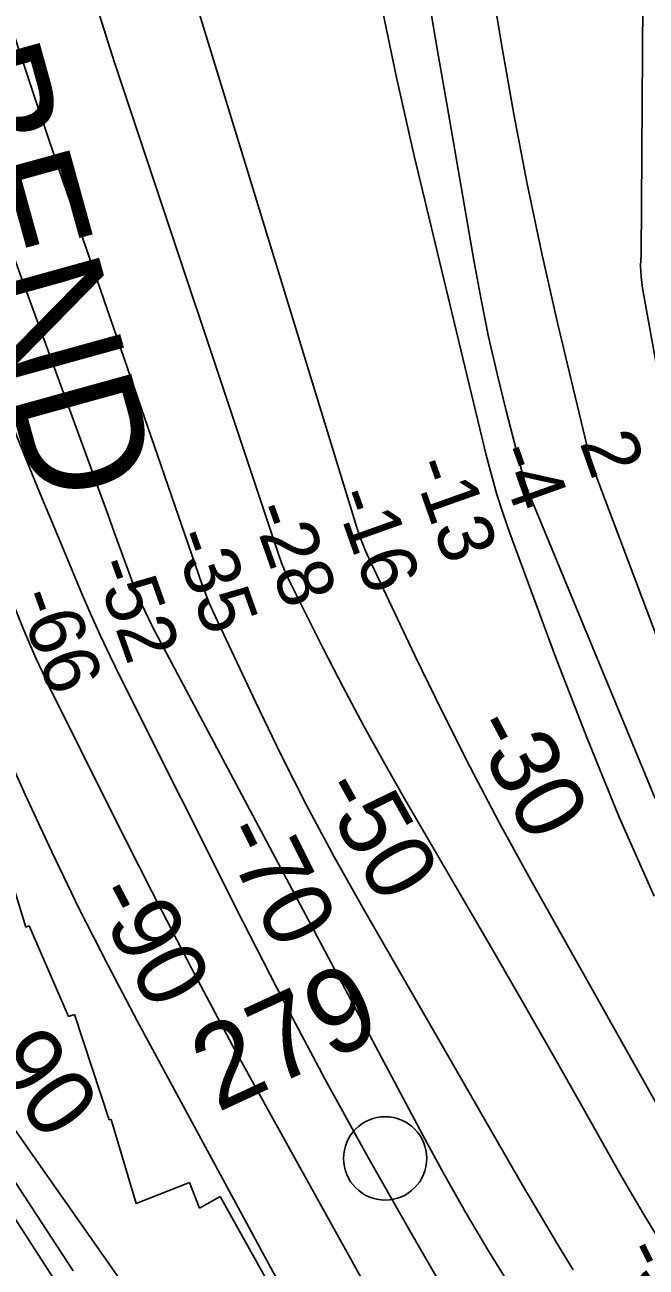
# Model space of a CAD drawing. Extents: x 3177185 to 3215018, y 812988 to 838321.
# Drawn here: x 3198092 to 3198839, y 819169 to 820661 of the extents above; entities that cross this region are included whole.
import ezdxf

# ---------------------------------------------------------------- set-up
doc = ezdxf.new("R2010")
doc.units = 0
for name, color, linetype in [('V-RIVR-IDEN', 7, 'Continuous'), ('V-RIVR-MILE', 7, 'Continuous'), ('V-RIVR-RANG', 7, 'Continuous'), ('V-RRAP-RVMT', 7, 'Continuous'), ('V-TOPO-DPTH', 7, 'Continuous'), ('V-TOPO-MAJR', 7, 'Continuous'), ('V-TOPO-MAJR-IDEN', 7, 'Continuous'), ('V-TOPO-MINR', 7, 'Continuous'), ('V-TOPO-MINR-IDEN', 7, 'Continuous')]:
    doc.layers.add(name, color=color, linetype=linetype)

msp = doc.modelspace()

# ---------------------------------------------------------------- linework, layer by layer
at = {"layer": 'V-RIVR-MILE'}
msp.add_circle((3198525.1, 819300), 50, dxfattribs=at)
at = {"layer": 'V-RRAP-RVMT'}
for p, q in [((3198093.6, 819577.8), (3198069.1, 819657.7)), ((3198097.4, 819579.5), (3198093.6, 819577.8)), ((3198144.8, 819470.4), (3198097.4, 819579.5)), ((3198152, 819472.8), (3198144.8, 819470.4)), ((3198193.7, 819346.2), (3198152, 819472.8)), ((3198196, 819346.8), (3198193.7, 819346.2)), ((3198226.1, 819246), (3198196, 819346.8)), ((3198289.9, 819271), (3198226.1, 819246)), ((3198302, 819240.3), (3198289.9, 819271)), ((3198326.8, 819254.1), (3198302, 819240.3)), ((3198381.1, 819157.2), (3198326.8, 819254.1))]:
    msp.add_line(p, q, dxfattribs=at)
at = {"layer": 'V-TOPO-DPTH'}
for points in [[(3198589.7, 821094.6), (3198664.8, 820638.2), (3198679.6, 820554.2), (3198695.5, 820470.3), (3198713.2, 820386.9), (3198732.2, 820303.6), (3198765.2, 820165), (3198768.7, 820151.3), (3198772.6, 820137.8), (3198777, 820124.3), (3198781.7, 820111), (3198927.4, 819724.6)], [(3198927.4, 819724.6), (3198781.7, 820111), (3198777, 820124.3), (3198772.6, 820137.8), (3198768.7, 820151.3), (3198765.2, 820165), (3198732.2, 820303.6), (3198713.2, 820386.9), (3198695.5, 820470.3), (3198679.6, 820554.2), (3198664.8, 820638.2), (3198589.7, 821094.6)], [(3198959.4, 819172.7), (3198698.1, 819637.9), (3198662.1, 819703.6), (3198627.1, 819769.7), (3198593.4, 819836.6), (3198560.7, 819904), (3198505.4, 820021.1), (3198501.2, 820030.4), (3198497.4, 820039.7), (3198493.9, 820049.2), (3198490.7, 820058.9), (3198209.4, 820976.5)], [(3198959.4, 819172.7), (3198698.1, 819637.9), (3198662.1, 819703.6), (3198627.1, 819769.7), (3198593.4, 819836.6), (3198560.7, 819904), (3198505.4, 820021.1), (3198501.2, 820030.4), (3198497.4, 820039.7), (3198493.9, 820049.2), (3198490.7, 820058.9), (3198209.4, 820976.5)], [(3198848.1, 819615), (3198806.3, 819709.8), (3198767.2, 819805.7), (3198729.9, 819902.4), (3198675, 820050.9), (3198666.9, 820074.1), (3198659.4, 820097.4), (3198652.7, 820120.9), (3198646.5, 820144.6), (3198560.1, 820504.1), (3198538.7, 820598.2), (3198519, 820692.6)], [(3198519, 820692.6), (3198538.7, 820598.2), (3198560.1, 820504.1), (3198646.5, 820144.6), (3198652.7, 820120.9), (3198659.4, 820097.4), (3198666.9, 820074.1), (3198675, 820050.9), (3198729.9, 819902.4), (3198767.2, 819805.7), (3198806.3, 819709.8), (3198848.1, 819615)], [(3198179.4, 820680.5), (3198200.1, 820616.3), (3198397.5, 820024.4), (3198400.7, 820015.4), (3198404.2, 820006.5), (3198408.1, 819997.8), (3198412.2, 819989.2), (3198450.6, 819912.6), (3198474.5, 819866.1), (3198499.1, 819819.8), (3198524.5, 819774), (3198550.4, 819728.5), (3198617.7, 819613.4), (3198654.4, 819550.1), (3198690.9, 819486.8), (3198727.1, 819423.3), (3198763.2, 819359.6), (3198807, 819281.9), (3198821.2, 819257.2), (3198835.7, 819232.7), (3198850.7, 819208.4)], [(3198850.7, 819208.4), (3198835.7, 819232.7), (3198821.2, 819257.2), (3198807, 819281.9), (3198763.2, 819359.6), (3198727.1, 819423.3), (3198690.9, 819486.8), (3198654.4, 819550.1), (3198617.7, 819613.4), (3198550.4, 819728.5), (3198524.5, 819774), (3198499.1, 819819.8), (3198474.5, 819866.1), (3198450.6, 819912.6), (3198412.2, 819989.2), (3198408.1, 819997.8), (3198404.2, 820006.5), (3198400.7, 820015.4), (3198397.5, 820024.4), (3198200.1, 820616.3), (3198179.4, 820680.5)]]:
    msp.add_lwpolyline(points, dxfattribs=at)
at = {"layer": 'V-TOPO-MAJR'}
msp.add_lwpolyline([(3198051, 820740.5), (3198076.4, 820658.8), (3198102.9, 820577.5), (3198130.3, 820496.4), (3198305, 819989.9), (3198308, 819981.6), (3198311.2, 819973.4), (3198314.6, 819965.2), (3198318.2, 819957.1), (3198369.6, 819847.6), (3198399.8, 819785.2), (3198431, 819723.4), (3198463.8, 819662.3), (3198497.7, 819601.9), (3198676.5, 819291.6), (3198690.2, 819267.9), (3198704, 819244.3), (3198718, 819220.7), (3198732, 819197.1), (3198741.2, 819181.7), (3198750.9, 819166)], dxfattribs=at)
at = {"layer": 'V-TOPO-MINR'}
for points in [[(3198860.7, 820199.1), (3198834.3, 820345.3), (3198832.7, 820358.6), (3198832, 820372), (3198832.7, 820385.3), (3198837.6, 821114.9), (3198836.6, 821140.9), (3198836.7, 821166.8), (3198837.4, 821192.8), (3198843.6, 821325)], [(3198927.4, 819724.6), (3198781.7, 820111), (3198777, 820124.3), (3198772.6, 820137.8), (3198768.7, 820151.3), (3198765.2, 820165), (3198732.2, 820303.6), (3198713.2, 820386.9), (3198695.5, 820470.3), (3198679.6, 820554.2), (3198664.8, 820638.2), (3198589.7, 821094.6)], [(3198959.4, 819172.7), (3198698.1, 819637.9), (3198662.1, 819703.6), (3198627.1, 819769.7), (3198593.4, 819836.6), (3198560.7, 819904), (3198505.4, 820021.1), (3198501.2, 820030.4), (3198497.4, 820039.7), (3198493.9, 820049.2), (3198490.7, 820058.9), (3198209.4, 820976.5)], [(3198360.5, 818935.1), (3198068.5, 819351.2), (3198037.5, 819393.6), (3198007.6, 819436.6), (3197979.4, 819480.8), (3197952.2, 819525.6), (3197829.3, 819737.2), (3197814.5, 819764.2), (3197800.7, 819791.7), (3197788.3, 819819.8), (3197776.8, 819848.3), (3197748.8, 819923.3), (3197725.3, 819990.1), (3197703.5, 820057.3), (3197684.2, 820125.4), (3197666.6, 820193.9), (3197501.7, 820888.3)], [(3197754.1, 820868.4), (3197895.1, 820450.9), (3197927.3, 820358.2), (3197960.6, 820265.9), (3197995.4, 820174.2), (3198031.3, 820082.8), (3198091.1, 819934.3), (3198098.1, 819917.6), (3198105.3, 819901), (3198112.9, 819884.6), (3198120.7, 819868.3), (3198197.6, 819713.7), (3198244.7, 819620.6), (3198292.7, 819527.8), (3198341.9, 819435.8), (3198392, 819344.2), (3198581.3, 819003.5), (3198585.8, 818995.5), (3198590.3, 818987.6), (3198594.9, 818979.8), (3198599.6, 818972), (3198834.6, 818587), (3198865.5, 818536.7)], [(3198127.2, 819155.3), (3198089.6, 819214), (3198050.8, 819272.1), (3198011.3, 819329.6), (3197975.2, 819381.2), (3197953.2, 819412.6), (3197931.3, 819444.1), (3197909.4, 819475.6), (3197887.6, 819507.2), (3197866.6, 819539.2), (3197846.6, 819571.8), (3197828.2, 819605.4), (3197810.7, 819639.5), (3197753.9, 819757.4), (3197750.5, 819764.9), (3197747.4, 819772.4), (3197744.6, 819780.1), (3197742.1, 819787.9), (3197466.6, 820701.7)], [(3197737.6, 820706.1), (3197773.2, 820594.8), (3197809.9, 820483.9), (3197848.3, 820373.5), (3197887.8, 820263.6), (3198025.3, 819889.3), (3198027.9, 819882.5), (3198030.6, 819875.7), (3198033.4, 819869), (3198036.3, 819862.3), (3198092.7, 819737.2), (3198124.6, 819668.3), (3198157.5, 819599.9), (3198191.9, 819532.3), (3198227.3, 819465.2), (3198504, 818953.8), (3198506.4, 818949.4), (3198508.8, 818945), (3198511.3, 818940.7), (3198513.8, 818936.3), (3198845.3, 818358.5)], [(3197964.8, 820699.4), (3197987.7, 820633.2), (3198011.3, 820567.1), (3198175.1, 820119.6), (3198183.4, 820096.7), (3198191.8, 820073.8), (3198200.1, 820050.9), (3198208.4, 820028), (3198218.7, 819999.7), (3198222, 819990.9), (3198225.4, 819982.3), (3198229, 819973.7), (3198232.8, 819965.1), (3198236.7, 819956.7), (3198240.8, 819948.3), (3198245, 819940), (3198249.3, 819931.7), (3198570.2, 819328.1), (3198595.5, 819281.6), (3198621.6, 819235.6), (3198648.6, 819190.1), (3198676.4, 819145)], [(3198848.1, 819615), (3198806.3, 819709.8), (3198767.2, 819805.7), (3198729.9, 819902.4), (3198675, 820050.9), (3198666.9, 820074.1), (3198659.4, 820097.4), (3198652.7, 820120.9), (3198646.5, 820144.6), (3198560.1, 820504.1), (3198538.7, 820598.2), (3198519, 820692.6)], [(3198849.5, 819732.1), (3198697.7, 820098.9), (3198695.7, 820104.3), (3198693.7, 820109.7), (3198692, 820115.2), (3198690.4, 820120.7), (3198670.5, 820197.9), (3198659.6, 820242.3), (3198649.4, 820286.7), (3198640.3, 820331.5), (3198632, 820376.3), (3198599, 820566.7), (3198588.1, 820630.4), (3198577.2, 820694.2)], [(3197894.2, 820672.7), (3197911.5, 820625.7), (3197928.9, 820578.8), (3198038.2, 820284), (3198060.8, 820224), (3198084, 820164.3), (3198108, 820104.8), (3198132.5, 820045.6), (3198161.3, 819977.2), (3198172, 819952.4), (3198183.1, 819927.8), (3198194.6, 819903.3), (3198206.5, 819879.1), (3198354.2, 819584.6), (3198403.1, 819489.4), (3198453, 819394.8), (3198504.7, 819301.2), (3198557.5, 819208.1), (3198646.8, 819053.8)], [(3198850.7, 819208.4), (3198835.7, 819232.7), (3198821.2, 819257.2), (3198807, 819281.9), (3198763.2, 819359.6), (3198727.1, 819423.3), (3198690.9, 819486.8), (3198654.4, 819550.1), (3198617.7, 819613.4), (3198550.4, 819728.5), (3198524.5, 819774), (3198499.1, 819819.8), (3198474.5, 819866.1), (3198450.6, 819912.6), (3198412.2, 819989.2), (3198408.1, 819997.8), (3198404.2, 820006.5), (3198400.7, 820015.4), (3198397.5, 820024.4), (3198200.1, 820616.3), (3198179.4, 820680.5)], [(3198150.3, 819165.1), (3198099.8, 819242.4), (3198048.9, 819319.5)]]:
    msp.add_lwpolyline(points, dxfattribs=at)

# ---------------------------------------------------------------- texts
at = {"layer": 'V-RIVR-IDEN'}
for s, height, rotation, p in [('BEND', 150, 285.4627, (3197961.2, 820615.5)), ('279', 100, 24.816, (3198323.4, 819354.8))]:
    msp.add_text(s, height=height, rotation=rotation, dxfattribs=at).set_placement(p)
at = {"layer": 'V-RIVR-RANG'}
for s, rotation, p in [('2', 289.5507, (3198758.3, 820159.9)), ('-4', 289.5507, (3198656.2, 820148.4)), ('-13', 289.5507, (3198555.7, 820132.5)), ('-16', 289.5507, (3198462.6, 820096)), ('-28', 289.5507, (3198362.6, 820078.8)), ('-35', 289.5507, (3198267.9, 820046.7)), ('-52', 289.5507, (3198173.8, 820012.6)), ('-66', 289.5507, (3198081.2, 819974.6)), ('-33', 296.2369, (3198808.8, 819188))]:
    msp.add_text(s, height=67, rotation=rotation, dxfattribs=at).set_placement(p)
at = {"layer": 'V-TOPO-MAJR-IDEN'}
msp.add_text('-50', height=83, rotation=299.2294, dxfattribs=at).set_placement((3198442.7, 819742.5))
at = {"layer": 'V-TOPO-MINR-IDEN'}
for s, rotation, p in [('-30', 297.9142, (3198625, 819817.8)), ('-70', 296.6391, (3198324.4, 819690.3)), ('-90', 297.7924, (3198171, 819616.4)), ('-90', 306.2012, (3198024.2, 819446.9))]:
    msp.add_text(s, height=83, rotation=rotation, dxfattribs=at).set_placement(p)

doc.saveas('drawing.dxf')
